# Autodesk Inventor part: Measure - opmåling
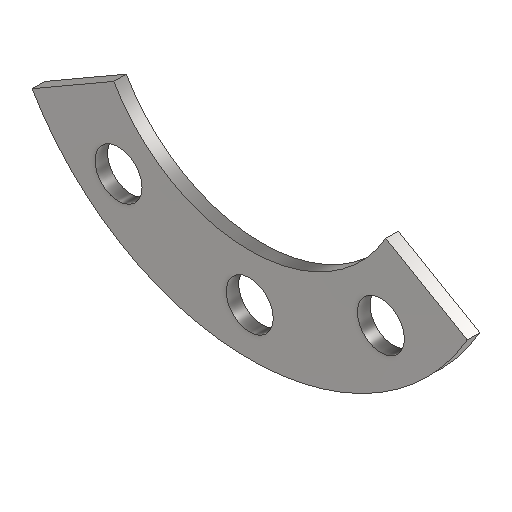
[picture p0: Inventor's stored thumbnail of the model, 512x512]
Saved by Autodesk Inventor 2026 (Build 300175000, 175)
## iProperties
Created: 2022-01
Part Number: Measure - opmåling
Material: Steel, Mild
Document SubType Name: Modeling
Designer: Lars Bertram Pedersen
Density: 7.85 g/cm^3
Appearance: Semi-Polished
Author: Lars Bertram Pedersen
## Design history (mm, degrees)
sketch "Sketch1"
  geometry: L1 (-21.651, -12.5)-(-34.641, -20); L2 (21.651, -12.5)-(34.641, -20); L3 (-21.651, -12.5)-(0, 0); L4 (0, 0)-(21.651, -12.5); L5 (0, 0)-(-20.891, -24.896); L6 (0, 0)-(20.891, -24.896); C1 r 3.75 at (-20.891, -24.896); C2 r 3.75 at (0, -32.5); C3 r 3.75 at (20.891, -24.896); A1 r 25 centre (0, 0) between (-21.651, -12.5) and (21.651, -12.5); A2 r 40 centre (0, 0) between (-34.641, -20) and (34.641, -20); A3 r 32.5 centre (0, 0) between (-28.146, -16.25) and (28.146, -16.25); 1 further point
  constraints: 12 end point, 10 point on circle, 6 centre point, 3 coincident, 2 collinear, 2 equal radius, 2 horizontal alignment, 1 midpoint, 1 vertical alignment
  dimensions: "d0" = 25 radius of A1; "d2" = 120 deg angle of L2 L1; "d3" = 20 deg angle of L5 L3; "d4" = 7.5 diameter of C1; "d5" = 15 distance of L1.start L1.end
extrude "Extrusion1" new body sketch "Sketch1" distance "d6" = 2; taper "d7" = 0 deg
body "Solid1"
